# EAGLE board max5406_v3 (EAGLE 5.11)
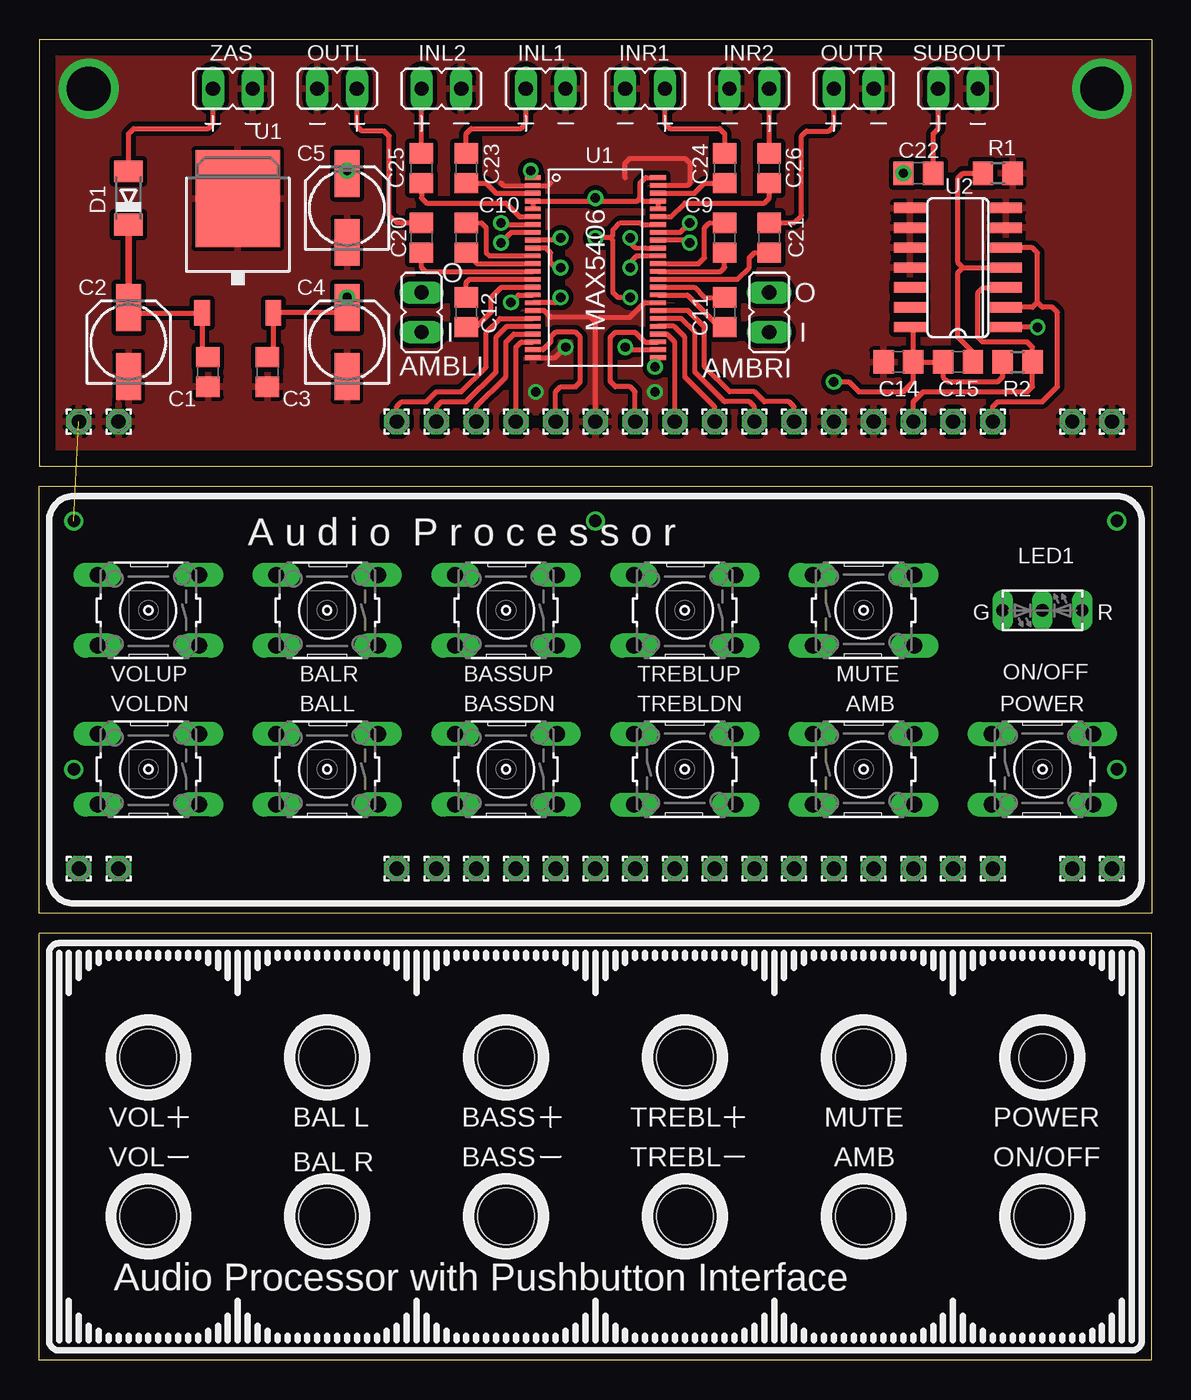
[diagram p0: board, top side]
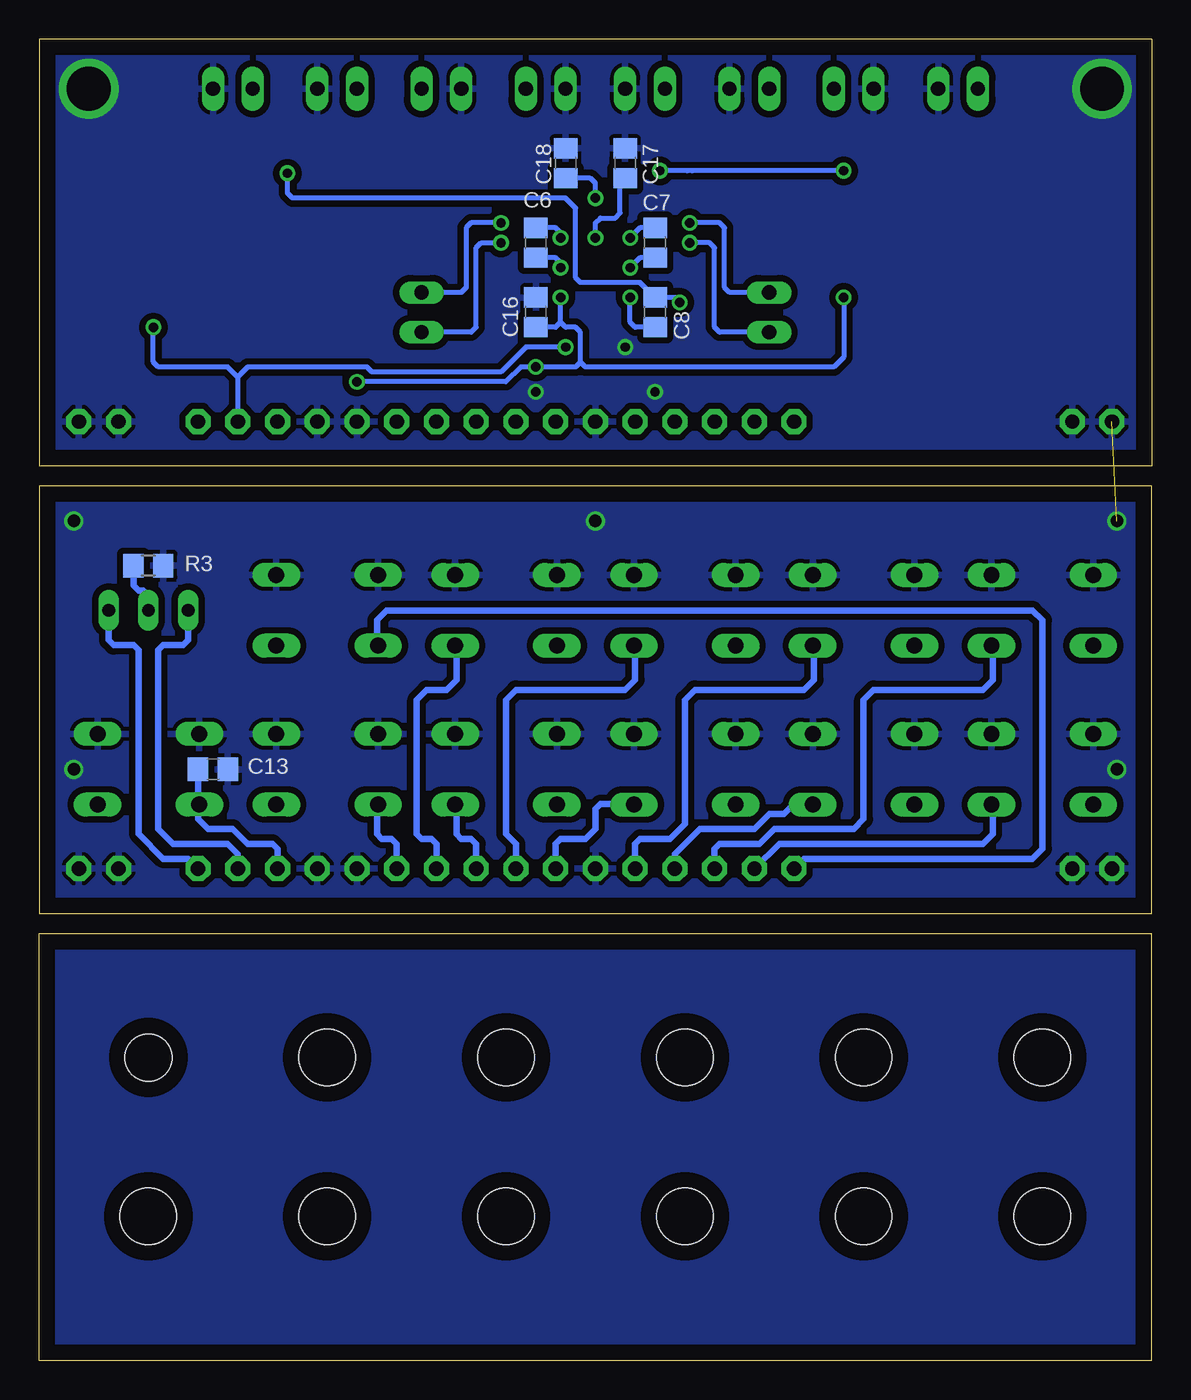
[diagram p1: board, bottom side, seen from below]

Size 71.12 x 84.45 mm. Coordinates in mm from the lower left corner, seen from the top.
Outline: 0,55.88 71.12,55.88 71.12,28.58 0,28.58 0,55.88
Outline: 0,57.15 71.12,57.15 71.12,84.45 0,84.45 0,57.15
Outline: 0,0 0,27.31 71.12,27.31 71.12,0 0,0
Copper layers (1*16): Top 0.035mm / dielectric 1.5mm / Bottom 0.035mm
Design rules "default": minimum track width 10mil, minimum drill 24mil, track to track 8mil, track to pad 8mil, pad to pad 8mil, via to via 8mil, smd to smd 8mil, copper to edge 40mil, drill to drill 8mil, minimum pad ring 10mil, minimum via ring 8mil, stop-mask expansion 4mil, vias tented up to drill 0mil, thermal gap 10mil
Holes 3.6 mm at 6.98,19.37 18.41,19.37 29.85,19.37 41.28,19.37 52.7,19.37 6.98,9.21 18.41,9.21 29.85,9.21 41.28,9.21 52.7,9.21 64.14,9.21
Holes 3 mm at 64.14,19.37

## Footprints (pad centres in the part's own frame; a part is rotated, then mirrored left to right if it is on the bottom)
B3F-10XX = drill 1.016 long: 1 -3.251,2.261; 2 3.251,2.261; 3 -3.251,-2.261; 4 3.251,-2.261
JP1 = drill 0.914 long: 1 0,-1.27; 2 0,1.27
C0805 = smd 1.3 x 1.5: 1 -0.95,0; 2 0.95,0
153CLV-0505 = smd 3 x 1.6: + 2.2,0; - -2.2,0
MINIMELF = smd 1.4 x 1.8: A 1.7,0; C -1.7,0
DUOLED2X5 = drill 0.813 long: AG -2.54,0; AR 2.54,0; K 0,0
1,6/0,9 = drill 0.914 pad 1.6 octagon: 1 0,0
R0805 = smd 1.3 x 1.5: 1 -0.95,0; 2 0.95,0
TO252 = smd 1 x 1.6: 1 -2.28,-4.8; 2 2.28,-4.8 | smd 5.4 x 6.2: 3 0,2.5
SO14 = smd 0.66 x 2.032: 1 -3.81,-3.073; 2 -2.54,-3.073; 3 -1.27,-3.073; 4 0,-3.073; 5 1.27,-3.073; 6 2.54,-3.073; 7 3.81,-3.073; 8 3.81,3.073; 9 2.54,3.073; 10 1.27,3.073; 11 0,3.073; 12 -1.27,3.073; 13 -2.54,3.073; 14 -3.81,3.073
MAX5406 = smd 0.305 x 1: 1 -5.75,-4; 2 -5.25,-4; 3 -4.75,-4; 4 -4.25,-4; 5 -3.75,-4; 6 -3.25,-4; 7 -2.75,-4; 8 -2.25,-4; 9 -1.75,-4; 10 -1.25,-4; 11 -0.75,-4; 12 -0.25,-4; 13 0.25,-4; 14 0.75,-4; 15 1.25,-4; 16 1.75,-4; 17 2.25,-4; 18 2.75,-4; 19 3.25,-4; 20 3.75,-4; 21 4.25,-4; 22 4.75,-4; 23 5.25,-4; 24 5.75,-4; 25 5.75,4; 26 5.25,4; 27 4.75,4; 28 4.25,4; 29 3.75,4; 30 3.25,4; 31 2.75,4; 32 2.25,4; 33 1.75,4; 34 1.25,4; 35 0.75,4; 36 0.25,4; 37 -0.25,4; 38 -0.75,4; 39 -1.25,4; 40 -1.75,4; 41 -2.25,4; 42 -2.75,4; 43 -3.25,4; 44 -3.75,4; 45 -4.25,4; 46 -4.75,4; 47 -5.25,4; 48 -5.75,4

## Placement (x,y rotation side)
AMB  [B3F-10XX]  52.7,37.78 0 top
AMBLI  [JP1]  24.45,66.99 180 top
AMBRI  [JP1]  46.67,66.99 180 top
BALL  [B3F-10XX]  18.41,37.78 180 top
BALR  [B3F-10XX]  18.41,47.94 180 top
BASSDN  [B3F-10XX]  29.85,37.78 180 top
BASSUP  [B3F-10XX]  29.85,47.94 180 top
C1  100n  [C0805]  10.79,63.18 270 top
C2  [153CLV-0505]  5.71,65.09 90 top
C3  100n  [C0805]  14.61,63.18 270 top
C4  [153CLV-0505]  19.68,65.09 90 top
C5  [153CLV-0505]  19.68,73.66 90 top
C6  4,7n  [C0805]  39.37,71.44 270 bottom
C7  4,7n  [C0805]  31.75,71.44 270 bottom
C8  150n  [C0805]  31.75,66.99 90 bottom
C9  3,3n  [C0805]  43.81,71.75 270 top
C10  3,3n  [C0805]  27.3,71.75 270 top
C11  1u  [C0805]  43.81,66.99 270 top
C12  1u  [C0805]  27.3,66.99 90 top
C13  100n  [C0805]  60.01,37.78 0 bottom
C14  100n  [C0805]  54.93,63.82 180 top
C15  1u  [C0805]  58.74,63.82 0 top
C16  1u  [C0805]  39.37,66.99 90 bottom
C17  [C0805]  33.66,76.52 90 bottom
C18  [C0805]  37.47,76.52 270 bottom
C20  [C0805]  24.45,71.75 90 top
C21  [C0805]  46.67,71.75 90 top
C22  150n  [C0805]  56.2,75.88 180 top
C23  [C0805]  27.3,76.2 270 top
C24  [C0805]  43.81,76.2 270 top
C25  [C0805]  24.45,76.2 270 top
C26  [C0805]  46.67,76.2 270 top
D1  [MINIMELF]  5.71,74.3 90 top
INL1  [JP1]  32.39,81.28 90 top
INL2  [JP1]  25.72,81.28 90 top
INR1  [JP1]  38.73,81.28 270 top
INR2  [JP1]  45.4,81.28 270 top
LED1  [DUOLED2X5]  64.14,47.94 0 top
MUTE  [B3F-10XX]  52.7,47.94 0 top
OUTL  [JP1]  19.05,81.28 90 top
OUTR  [JP1]  52.07,81.28 270 top
PAD1  [1,6/0,9]  25.4,60.01 90 top
PAD2  [1,6/0,9]  25.4,31.43 90 top
PAD3  [1,6/0,9]  27.94,60.01 90 top
PAD4  [1,6/0,9]  27.94,31.43 90 top
PAD5  [1,6/0,9]  30.48,60.01 90 top
PAD6  [1,6/0,9]  30.48,31.43 90 top
PAD7  [1,6/0,9]  33.02,60.01 90 top
PAD8  [1,6/0,9]  33.02,31.43 90 top
PAD9  [1,6/0,9]  43.18,60.01 90 top
PAD10  [1,6/0,9]  43.18,31.43 90 top
PAD11  [1,6/0,9]  45.72,60.01 90 top
PAD12  [1,6/0,9]  45.72,31.43 90 top
PAD13  [1,6/0,9]  38.1,60.01 90 top
PAD14  [1,6/0,9]  38.1,31.43 90 top
PAD15  [1,6/0,9]  40.64,60.01 90 top
PAD16  [1,6/0,9]  40.64,31.43 90 top
PAD17  [1,6/0,9]  22.86,60.01 90 top
PAD18  [1,6/0,9]  22.86,31.43 90 top
PAD19  [1,6/0,9]  48.26,60.01 90 top
PAD20  [1,6/0,9]  48.26,31.43 90 top
PAD21  [1,6/0,9]  35.56,60.01 90 top
PAD22  [1,6/0,9]  35.56,31.43 90 top
PAD23  [1,6/0,9]  58.42,60.01 270 top
PAD24  [1,6/0,9]  58.42,31.43 270 top
PAD25  [1,6/0,9]  55.88,60.01 270 top
PAD26  [1,6/0,9]  55.88,31.43 270 top
PAD27  [1,6/0,9]  60.96,60.01 270 top
PAD28  [1,6/0,9]  60.96,31.43 270 top
PAD29  [1,6/0,9]  50.8,60.01 0 top
PAD30  [1,6/0,9]  50.8,31.43 0 top
PAD31  [1,6/0,9]  53.34,60.01 0 top
PAD32  [1,6/0,9]  53.34,31.43 0 top
PAD33  [1,6/0,9]  2.54,31.43 0 top
PAD34  [1,6/0,9]  68.58,60.01 0 top
PAD35  [1,6/0,9]  68.58,31.43 0 top
PAD36  [1,6/0,9]  2.54,60.01 0 top
PAD37  [1,6/0,9]  5.08,31.43 0 top
PAD38  [1,6/0,9]  5.08,60.01 0 top
PAD39  [1,6/0,9]  66.04,60.01 0 top
PAD40  [1,6/0,9]  66.04,31.43 0 top
POWER  [B3F-10XX]  64.14,37.78 0 top
R1  10k  [R0805]  61.28,75.88 0 top
R2  10k  [R0805]  62.55,63.82 0 top
R3  470  [R0805]  64.14,50.8 180 bottom
SUBOUT  [JP1]  58.74,81.28 270 top
TREBLDN  [B3F-10XX]  41.28,37.78 0 top
TREBLUP  [B3F-10XX]  41.28,47.94 180 top
U1  7805DT  [TO252]  12.7,71.75 0 top
U2  4013D  [SO14]  58.74,69.85 90 top
U$1  MAX5406  [MAX5406]  35.56,69.85 270 top
VOLDN  [B3F-10XX]  6.98,37.78 180 top
VOLUP  [B3F-10XX]  6.98,47.94 180 top
ZAS  [JP1]  12.38,81.28 90 top

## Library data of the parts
AMB BALL BALR BASSDN BASSUP MUTE POWER TREBLDN TREBLUP VOLDN VOLUP = switch-omron
AMBLI AMBRI INL1 INL2 INR1 INR2 OUTL OUTR SUBOUT ZAS = jumper
C1-C18 C20-C26 R1-R3 = rcl
D1 = diode
LED1 = led
PAD1-PAD40 = wirepad
U1 = linear
U2 = 40xx
U$1 = max5406

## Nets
123: AMB.1 AMB.2 BALL.3 BALL.4 BALR.3 BALR.4 BASSDN.3 BASSDN.4 BASSUP.3 BASSUP.4 C1.2 C2.- C3.2 C4.- C5.- C13.2 C14.2 C16.2 C17.2 C18.1 INL1.1 INL2.1 INR1.1 INR2.1 MUTE.1 MUTE.2 OUTL.2 OUTR.2 PAD21.1 PAD22.1 PAD29.1 PAD30.1 PAD31.1 PAD32.1 PAD33.1 PAD34.1 PAD35.1 PAD36.1 PAD37.1 PAD38.1 PAD39.1 PAD40.1 POWER.1 POWER.2 R1.2 R3.1 SUBOUT.2 TREBLDN.1 TREBLDN.2 TREBLUP.3 TREBLUP.4 U1.3 U2.6 U2.7 U2.8 U2.9 U2.10 U2.11 U$1.2 U$1.18 U$1.24 U$1.32 U$1.47 VOLDN.3 VOLDN.4 VOLUP.3 VOLUP.4 ZAS.1
N$2: C20.1 U$1.13
N$3: C21.1 U$1.35
N$4: C20.2 OUTL.1
N$5: C21.2 OUTR.1
N$6: C22.1 SUBOUT.1
N$7: PAD1.1 U$1.20
N$8: PAD3.1 U$1.21
N$9: PAD5.1 U$1.22
N$10: PAD7.1 U$1.23
N$11: PAD9.1 U$1.29
N$12: PAD11.1 U$1.30
N$13: PAD13.1 U$1.27
N$14: PAD15.1 U$1.28
N$15: PAD17.1 U$1.19
N$16: PAD19.1 U$1.31
N$17: PAD2.1 VOLDN.1
N$18: PAD4.1 VOLUP.1
N$19: BALL.1 PAD6.1
N$20: BALR.1 PAD8.1
N$21: PAD10.1 TREBLDN.4
N$22: PAD12.1 TREBLUP.1
N$23: BASSDN.1 PAD14.1
N$24: BASSUP.1 PAD16.1
N$25: MUTE.3 PAD18.1
N$26: AMB.3 PAD20.1
N$27: PAD23.1 U2.1 U$1.26
N$28: C5.+ U$1.1
N$29: C23.1 INL1.2
N$30: C18.2 U$1.4 U$1.5 U$1.44 U$1.45 U$1.48
N$31: C24.1 INR1.2
N$32: C25.1 INL2.2
N$33: C26.1 INR2.2
N$34: C26.2 U$1.43
N$35: C25.2 U$1.6
N$36: C24.2 U$1.46
N$37: D1.A ZAS.2
N$38: C1.1 C2.+ D1.C U1.1
N$39: C3.1 C4.+ C14.1 C15.1 C16.1 C17.1 R2.1 U1.2 U2.14 U$1.25 U$1.42
N$40: LED1.K R3.2
N$41: C6.1 U$1.39
N$42: C7.1 U$1.9
N$43: C6.2 U$1.38
N$44: C7.2 U$1.10
N$45: PAD27.1 U2.2 U2.5
N$46: C8.2 C22.2 U$1.16
N$47: C9.1 U$1.37
N$48: C9.2 U$1.36
N$49: C10.1 U$1.11
N$50: C10.2 U$1.12
N$51: C11.1 U$1.34
N$52: C11.2 U$1.33
N$53: C12.2 U$1.14
N$54: C12.1 U$1.15
N$55: C8.1 U$1.17
N$56: PAD25.1 R2.2 U2.3
N$57: C13.1 PAD26.1 POWER.3
N$58: LED1.AG PAD24.1
N$59: LED1.AR PAD28.1
N$60: C15.2 R1.1 U2.4
N$61: C23.2 U$1.3
N$62: AMBLI.1 U$1.7
N$63: AMBRI.2 U$1.40
N$64: AMBLI.2 U$1.8
N$65: AMBRI.1 U$1.41

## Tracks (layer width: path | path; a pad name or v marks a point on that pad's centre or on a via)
123  (via drill 0.6, 0.8, 2.8)  (1 unrouted)
  Top 0.305: U$1.18 32.28,67.1 32.7,66.68 35.24,66.68 35.56,66.36 | U$1.32 38.71,67.6 37.78,66.68 35.88,66.68 35.56,66.36 | U$1.24 32.99,64.1 v33.65,64.77 | PAD21.1 35.56,66.36 | 32.7,75.25 32.56,75.1 U$1.2 29.68,75.1 29.53,75.25 | U$1.47 41.44,75.1 41.59,75.25 41.59,76.52 41.28,76.83 37.78,76.83 37.47,76.52 37.47,75.57
  other vias: 3.17,81.28 67.95,81.28 31.75,61.91 39.37,61.91 2.22,53.66 2.22,37.78 68.9,37.78 68.9,53.66 35.56,53.66
  pour Bottom (isolate 0.406): -0.32,56.2 71.44,56.2 71.44,28.26 -0.32,28.26
  pour Top (isolate 0.305): -0.32,85.09 71.44,85.09 71.44,57.15 -0.32,57.15
  pour Bottom (isolate 0.406): -0.32,85.41 71.44,85.41 71.44,57.15 -0.32,57.15
N$1
  pour Bottom: -0.32,27.62 71.44,27.62 71.44,-0.32 -0.32,-0.32
N$2
  Top 0.305: U$1.13 24.7,69.6 24.45,69.85 C20.1
N$3
  Top 0.305: U$1.35 44.65,69.1 45.4,69.85 45.4,70.48 45.72,70.8 C21.1
N$4
  Top 0.305: OUTL.1 20.32,78.9 20.64,78.58 22.07,78.58 22.38,78.26 22.38,76.2 22.38,73.18 22.86,72.71 C20.2
N$5
  Top 0.305: OUTR.1 50.8,78.9 50.48,78.58 49.05,78.58 48.74,78.26 48.74,76.2 48.74,73.18 48.26,72.71 46.35,72.71 C21.2
N$6
  Top 0.305: C22.1 57.15,78.42 57.47,78.74 SUBOUT.1
N$7
  Top 0.305: U$1.20 29.9,66.1 29.21,65.4 29.21,63.18 27.3,61.28 25.72,61.28 25.4,60.96 PAD1.1
N$8
  Top 0.305: U$1.21 30.36,65.6 29.85,65.09 29.85,62.87 27.94,60.96 PAD3.1
N$9
  Top 0.305: U$1.22 30.81,65.1 30.48,64.77 PAD5.1
N$10
  Top 0.305: PAD7.1 33.02,61.91 33.34,62.23 34.29,62.23 34.61,62.55 34.61,65.4 34.29,65.72 33.02,65.72 32.7,65.4 32.7,65.09 32.22,64.6 U$1.23
N$11
  Top 0.305: U$1.29 40.58,66.1 41.28,65.4 41.28,62.87 43.18,60.96 PAD9.1
N$12
  Top 0.305: U$1.30 41.03,66.6 41.91,65.72 41.91,63.18 43.82,61.28 45.4,61.28 45.72,60.96 PAD11.1
N$13
  Top 0.305: PAD13.1 38.1,61.91 37.78,62.23 36.83,62.23 36.51,62.55 36.51,65.4 36.83,65.72 38.1,65.72 38.72,65.1 U$1.27
N$14
  Top 0.305: U$1.28 40.13,65.6 40.64,65.09 PAD15.1
N$15
  Top 0.305: U$1.19 29.45,66.6 28.57,65.72 28.57,63.5 26.99,61.91 25.4,61.91 24.77,61.28 23.18,61.28 22.86,60.96 PAD17.1
N$16
  Top 0.305: U$1.31 41.49,67.1 42.54,66.04 42.54,63.5 44.13,61.91 45.72,61.91 46.36,61.28 47.94,61.28 48.26,60.96 PAD19.1
N$17
  Bottom 0.406: VOLDN.1 10.16,35.28 10.16,33.66 10.8,33.02 23.81,33.02 PAD2.1
N$18
  Bottom 0.406: VOLUP.1 10.16,45.61 10.16,43.5 10.8,42.86 17.78,42.86 18.41,42.23 18.41,34.61 19.05,33.97 24.13,33.97 25.08,33.02 27.62,33.02 27.94,32.7 PAD4.1
N$19
  Bottom 0.406: PAD6.1 30.48,32.39 28.89,33.97 25.4,33.97 24.45,34.93 23.5,34.93 22.86,35.56 21.7,35.56 BALL.1
N$20
  Bottom 0.406: BALR.1 21.59,45.61 21.59,43.5 22.23,42.86 29.21,42.86 29.85,42.23 29.85,34.29 30.8,33.34 32.7,33.34 33.02,33.02 PAD8.1
N$21
  Bottom 0.406: PAD10.1 43.18,33.02 43.5,33.34 44.13,33.34 44.45,33.66 44.45,35.45 TREBLDN.4
N$22
  Bottom 0.406: TREBLUP.1 44.45,45.61 44.45,43.5 45.08,42.86 46.36,42.86 46.99,42.23 46.99,33.66 46.67,33.34 46.04,33.34 45.72,33.02 PAD12.1
N$23
  Bottom 0.406: PAD14.1 38.1,33.02 37.78,33.34 36.19,33.34 35.56,33.97 35.56,35.24 35.24,35.56 33.13,35.56 BASSDN.1
N$24
  Bottom 0.406: BASSUP.1 33.02,45.61 33.02,43.5 33.65,42.86 40.64,42.86 41.28,42.23 41.28,33.66 40.64,33.02 PAD16.1
N$25
  Bottom 0.406: PAD18.1 22.23,32.07 7.62,32.07 6.98,32.7 6.98,47.31 7.62,47.94 48.89,47.94 49.53,47.31 49.53,45.76 MUTE.3
N$26
  Bottom 0.406: PAD20.1 48.26,33.02 48.58,33.34 49.21,33.34 49.53,33.66 49.53,35.45 AMB.3
N$27  (via drill 0.6)
  Top 0.305: U$1.26 37.64,64.6 v37.47,64.77 | v63.82,66.04 U2.1
  Bottom 0.305: v37.47,64.77 40,64.77 41.59,63.18 49.85,63.18 50.17,63.5 57.79,63.5 58.42,62.87 | 58.42,62.87 PAD23.1 | 58.42,62.87 59.06,63.5 63.5,63.5 63.82,63.82 v63.82,66.04
N$28  (via drill 0.6)
  Top 0.305: U$1.1 31.4,75.6 31.43,75.88 v31.43,76.04 | C5.+ v19.68,76.04
  Bottom 0.305: v31.43,76.04 29.69,76.04 29.37,76.04 20,76.04 19.84,76.04 v19.68,76.04 19.68,76.18
N$29
  Top 0.305: C23.1 27.3,78.42 27.62,78.74 30.8,78.74 31.11,79.06 INL1.2
N$30  (via drill 0.6)
  Top 0.305: 39.88,75.6 U$1.48 38.77,75.6 38.42,75.25 38.42,74.3 | U$1.5 U$1.4 35.36,74.1 v35.56,74.3 35.75,74.1 38.22,74.1 38.42,74.3 | U$1.44 U$1.45 38.61,74.1 38.42,74.3
  Bottom 0.305: v35.56,74.3 35.56,75.25 35.88,75.57 C18.2
N$31
  Top 0.305: C24.1 43.82,78.42 43.5,78.74 40.32,78.74 40,79.06 INR1.2
N$32
  Top 0.305: C25.1 INL2.2
N$33
  Top 0.305: C26.1 INR2.2
N$34
  Top 0.305: U$1.43 40.4,73.1 41.28,73.98 46.36,73.98 46.67,74.3 C26.2
N$35
  Top 0.305: U$1.6 30.72,73.1 29.85,73.98 24.77,73.98 24.45,74.3 C25.2
N$36
  Top 0.305: U$1.46 41.9,74.6 42.54,75.25 C24.2
N$37
  Top 0.305: ZAS.2 11.11,79.06 10.8,78.74 6.03,78.74 5.72,78.42 D1.A
N$38
  Top 0.305: C1.1 10.42,64.19 U1.1 6.05,66.95 C2.+
  Top 0.406: C2.+ D1.C
N$39  (via drill 0.6)
  Top 0.305: 14.98,66.94 U1.2 | C3.1 14.98,64.19 14.98,66.94 | v19.68,67.94 C4.+ 19.39,66.99 14.92,66.99 14.98,66.94 | v37.78,67.94 36.99,67.94 36.67,68.26 36.67,71.6 36.51,71.76 | 55.57,65.94 U2.14 55.88,65.83 C14.1 | U$1.25 39.56,63.69 v39.37,63.5 | C14.1 C15.1 57.79,62.87 58.1,62.55 61.28,62.55 61.6,62.87 R2.1 | v50.8,62.55 51.75,62.55 52.39,61.91 55.25,61.91 55.88,62.55 55.88,64.45 C14.1 | U$1.42 38.53,72.6 38.42,72.71 37.15,72.71 36.67,72.23 36.67,71.91 36.51,71.76 | 36.51,71.76 v35.56,71.76
  Bottom 0.305: v19.68,67.94 19.68,64.13 20.32,63.5 36.19,63.5 36.51,63.82 | v50.8,62.55 41.28,62.55 40.32,63.5 v39.37,63.5 36.83,63.5 36.51,63.82 | 38.74,66.04 C16.1 | 38.74,66.04 38.73,66.04 | 36.51,63.82 36.51,65.72 36.83,66.04 37.47,66.04 37.78,66.36 | 37.78,66.36 v37.78,67.94 | 38.74,66.04 38.1,66.04 37.78,66.36 | C17.1 33.97,75.57 33.97,73.34 34.29,73.02 35.24,73.02 35.56,72.71 v35.56,71.76
N$40
  Bottom 0.406: R3.2 65.09,49.53 64.77,49.21 64.45,49.21 64.14,48.9 LED1.K
N$41  (via drill 0.6)
  Top 0.305: U$1.39 38.75,71.1 38.1,71.12 37.78,71.44 v37.78,71.76
  Bottom 0.305: v37.78,71.76 37.78,72.07 38.1,72.39 C6.1
N$42  (via drill 0.6)
  Top 0.305: 31.59,71.6 U$1.9 33.18,71.6 v33.34,71.76
  Bottom 0.305: C7.1 32.7,72.39 v33.34,71.76
N$43  (via drill 0.6)
  Top 0.305: v37.78,69.85 37.78,70.17 38.22,70.6 U$1.38
  Bottom 0.305: v37.78,69.85 37.78,70.17 38.1,70.48 C6.2
N$44  (via drill 0.6)
  Top 0.305: v33.34,69.85 33.02,69.85 32.7,70.17 32.7,70.8 32.4,71.1 U$1.10
  Bottom 0.305: C7.2 32.7,70.48 v33.34,69.85
N$45
  Top 0.305: U2.5 63.5,71.12 63.82,70.8 63.82,67.63 | 63.82,67.63 63.5,67.31 U2.2 | 63.82,67.63 64.14,67.31 64.77,67.31 65.09,66.99 65.09,62.23 64.14,61.28 61.28,61.28 60.96,60.96 PAD27.1
N$46  (via drill 0.6)
  Top 0.305: U$1.16 30.64,68.1 v30.16,67.63 | C22.2
  Bottom 0.305: C22.2 55.25,74.61 54.93,74.3 37.47,74.3 36.83,73.66 36.83,69.22 36.51,68.9 32.71,68.9 C8.2 30.16,67.94 v30.16,67.63 30.48,67.94
  other vias: 55.25,75.88
N$47
  Top 0.305: U$1.37 42.16,70.1 42.54,70.48 42.54,72.39 42.86,72.71 C9.1
N$48
  Top 0.305: U$1.36 43.57,69.6 43.82,69.85 C9.2
N$49
  Top 0.305: U$1.11 28.78,70.6 28.57,70.8 28.57,72.39 28.26,72.71 | C10.1 28.26,72.71 | 28.26,72.71
N$50
  Top 0.305: U$1.12 28.01,70.1 C10.2
N$51
  Top 0.305: U$1.34 41.89,68.6 42.54,67.94 C11.1
N$52
  Top 0.305: U$1.33 41.44,68.1 43.18,66.36 43.5,66.36 C11.2
N$53
  Top 0.305: U$1.14 27.51,69.1 27.3,68.9 C12.2
N$54
  Top 0.305: U$1.15 29.55,68.6 28.89,67.94 28.89,66.99 27.94,66.04 C12.1
N$55  (via drill 0.6)
  Top 0.305: U$1.17 32.99,67.6 v33.34,67.94
  Bottom 0.305: v33.34,67.94 33.34,66.36 33.02,66.04 C8.1
N$56
  Top 0.305: U2.3 60.32,68.58 60.01,68.26 60.01,65.4 60.32,65.09 63.18,65.09 63.5,64.77 63.5,64.45 R2.2 63.5,64.45 63.5,62.23 63.18,61.91 56.51,61.91 55.88,61.28 PAD25.1
N$57
  Bottom 0.406: C13.1 60.96,35.6 POWER.3 60.96,35.45 60.96,34.61 60.32,33.97 58.74,33.97 57.79,33.02 56.2,33.02 55.88,32.7 PAD26.1
N$58
  Bottom 0.406: LED1.AG 61.6,46.04 61.91,45.72 63.18,45.72 63.5,45.4 63.5,33.97 62.55,33.02 59.06,33.02 58.42,32.39 PAD24.1
N$59
  Bottom 0.406: LED1.AR 66.67,46.04 66.36,45.72 65.09,45.72 64.77,45.4 64.77,33.66 63.18,32.07 61.6,32.07 PAD28.1
N$60
  Top 0.305: 59.06,69.85 U2.4 | 59.06,69.85 58.74,69.53 58.74,65.4 59.69,64.45 | 59.06,69.85 58.74,70.17 58.74,75.57 59.06,75.88 R1.1 | C15.2 59.69,64.45 | 59.69,64.45
N$61
  Top 0.305: U$1.3 29.22,74.6 28.57,75.25 C23.2
N$62  (via drill 0.6)
  Top 0.305: U$1.7 29.64,72.6 v29.53,72.71
  Bottom 0.305: v29.53,72.71 27.62,72.71 27.3,72.39 27.3,68.58 26.99,68.26 AMBLI.1
N$63  (via drill 0.6)
  Top 0.305: U$1.40 41.11,71.6 v41.59,71.44
  Bottom 0.305: AMBRI.2 43.5,65.72 43.18,66.04 43.18,71.12 42.86,71.44 v41.59,71.44
N$64  (via drill 0.6)
  Top 0.305: U$1.8 30.19,72.1 v29.53,71.44
  Bottom 0.305: AMBLI.2 27.62,65.72 27.94,66.04 27.94,71.12 28.26,71.44 v29.53,71.44
N$65  (via drill 0.6)
  Top 0.305: U$1.41 40.99,72.1 v41.59,72.71
  Bottom 0.305: v41.59,72.71 43.5,72.71 43.82,72.39 43.82,68.58 44.13,68.26 AMBRI.1

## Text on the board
tPlace: A u d i o P r o c e s s o r | G | R | ON/OFF | VOL | BAL L | BASS | TREBL | MUTE | POWER | VOL | BAL R | BASS | TREBL | AMB | ON/OFF | Audio Processor with Pushbutton Interface
tNames: U1 | O | O | I | I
